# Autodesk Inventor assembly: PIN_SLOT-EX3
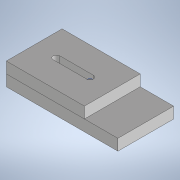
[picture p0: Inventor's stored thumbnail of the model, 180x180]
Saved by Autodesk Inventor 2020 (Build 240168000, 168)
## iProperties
Created: 2023-07
Part Number: PIN_SLOT-EX3
Document SubType Name: Assembly
Designer: chae-won
Author: chae-won
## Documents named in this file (4)
- C:\Users\chae-won\Desktop\설계도면\PIN_SLOT\PIN_SLOT-EX3.iam
- C:\Users\chae-won\Desktop\설계도면\PIN_SLOT\BASE.ipt
- C:\Users\chae-won\Desktop\설계도면\PIN_SLOT\PIN_8-12.ipt
- C:\Users\chae-won\Desktop\설계도면\PIN_SLOT\SLIDE.ipt
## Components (3 placed, 3 different names)
1. BASE:1 — 플러쉬:1, 플러쉬:2, 플러쉬:3, 플러쉬:5
2. PIN_8-12:1 — 플러쉬:1
3. SLIDE:1 — 플러쉬:2, 플러쉬:3, 플러쉬:5
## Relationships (4: Flush 4)
- 플러쉬:1 [Flush]: BASE:1 ↔ PIN_8-12:1
- 플러쉬:2 [Flush]: BASE:1 ↔ SLIDE:1
- 플러쉬:3 [Flush]: BASE:1 ↔ SLIDE:1
- 플러쉬:5 [Flush]: BASE:1 ↔ SLIDE:1
